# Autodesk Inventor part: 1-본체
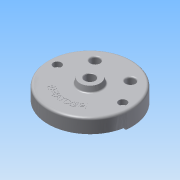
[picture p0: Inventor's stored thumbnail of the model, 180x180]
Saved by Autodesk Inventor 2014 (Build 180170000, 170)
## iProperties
Created: 2015-06
Part Number: 1-본체
Material: 알루미늄 6061
Document SubType Name: Modeling
Designer: Administrator
Density: 2.71 g/cm^3
Appearance: 알루미늄 - 평지
Mass: 1431.69 g
Surface Area: 1069.45 cm^2
Volume: 528.298 cm^3
Author: Administrator
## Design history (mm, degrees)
sketch "스케치1"
  geometry: C1 r 95 at (0, 0); 1 further point
  constraints: 1 centre point, 1 coincident
  dimensions: "d0" = 190 diameter of C1
extrude "돌출1" new body sketch "스케치1" distance "d1" = 32; taper "d2" = 0 deg
feature "쉘1" dims "d3" = 19, "d4" = 5
sketch "스케치2"
  geometry: C1 r 95 at (0, 0) reference; C2 r 26 at (0, 0)
  constraints: 1 centre point, 1 coincident
  dimensions: "d5" = 52 diameter of C2
extrude "돌출2" join sketch "스케치2" distance "d6" = 12; taper "d7" = -15 deg
sketch "스케치3"
  geometry: C1 r 90 at (0, 0) reference; C2 r 35 at (0, 0)
  constraints: 1 centre point, 1 coincident
  dimensions: "d8" = 70 diameter of C2
extrude "돌출3" join sketch "스케치3" distance "d9" = 10; taper "d10" = 0 deg
hole "구멍1" diameter "d13" = 23; stored, may be unused: countersink angle "d17" = 90 deg, drill point angle "d19" = 0 deg; dims "d11" = 10, "d12" = 10, "d14" = 6, "d15" = 50, "d16" = 15, "d18" = 8
sketch "스케치4"
  geometry: L1 (-45.033, 16)-(-75.657, 16); L2 (45.033, 16)-(75.657, 16); C1 r 95 at (0, 0) reference; A1 r 90 centre (0, 0) between (-88.566, 16) and (88.566, 16) reference; A2 r 42 centre (0, 0) between (36.373, 21) and (-36.373, 21); A3 r 90 centre (0, 0) between (85.114, 29.25) and (-85.114, 29.25); A4 r 10 centre (-75.657, 26) between (-85.114, 29.25) and (-75.657, 16); A5 r 10 centre (75.657, 26) between (75.657, 16) and (85.114, 29.25); A6 r 10 centre (-45.033, 26) between (-45.033, 16) and (-36.373, 21); A7 r 10 centre (45.033, 26) between (36.373, 21) and (45.033, 16); 2 further points
  constraints: 18 point on circle, 8 tangent, 6 centre point, 4 end point, 4 point on line, 3 equal radius, 2 coincident, 2 collinear, 1 horizontal
  dimensions: "d20" = 84 diameter of A2; "d21" = 16 distance from line of A1.centre L1; "d22" = 10 radius of A4; "d23" = 10 radius of A6
extrude "돌출4" cut sketch "스케치4" distance "d24" = 20; taper "d25" = 0 deg
sketch "스케치5"
  geometry: L1 (-45.033, 16)-(-75.657, 16) reference; L2 (-59, -19)-(59, -19); L3 (-59, -19)-(-59, -14); L4 (-41, -19)-(-41, -14); L5 (0, -19)-(0, 0); L6 (59, -19)-(59, -14); L7 (41, -19)-(41, -14); C1 r 35 at (0, 0) reference; A1 r 90 centre (0, 0) between (-85.114, 29.25) and (85.114, 29.25) reference; A2 r 41 centre (0, -19) between (-41, -19) and (41, -19); A3 r 59 centre (0, -19) between (-59, -19) and (59, -19); A4 r 9 centre (-50, -14) between (-41, -14) and (-59, -14); A5 r 9 centre (50, -14) between (59, -14) and (41, -14)
  constraints: 12 end point, 8 point on circle, 4 centre point, 4 parallel, 4 tangent, 3 symmetric about line, 2 point on line, 1 coincident, 1 perpendicular, 1 vertical alignment, 1 other
  dimensions: "d27" = 19 distance of A2.centre A1.centre; "d29" = 5 distance of L2.start L3.end; "d30" = 41 radius of A2; "d31" = 59 radius of A3
extrude "돌출5" cut sketch "스케치5" distance "d32" = 7; taper "d33" = 0 deg
sketch "스케치6"
  geometry: C1 r 90 at (0, 0) reference; C2 r 9 at (-74, 0); C3 r 9 at (74, 0)
  constraints: 2 centre point, 2 horizontal alignment, 1 equal radius
  dimensions: "d34" = 18 diameter of C2; "d35" = 148 distance of C3.centre C2.centre; "d36" = 74 distance of C3.centre C1.centre
extrude "돌출6" join sketch "스케치6" stored distance "d37" = 7; taper "d38" = 0 deg
sketch "스케치7"
  geometry: C1 r 9 at (-74, 0) reference; C2 r 9 at (74, 0) reference; 2 further points
  constraints: 2 coincident
hole "구멍2" sketch "스케치7" at (-74, 0), (74, 0) diameter "d39" = 11; stored, may be unused: countersink angle "d43" = 90 deg, drill point angle "d45" = 0 deg; dims "d40" = 6, "d41" = 18, "d42" = 11, "d44" = 8
sketch "스케치8"
  geometry: C1 r 90 at (0, 0); C2 r 15 at (-40, 52); C3 r 15 at (40, 52); C4 r 9 at (-74, 0)
  constraints: 4 centre point, 1 equal radius, 1 horizontal alignment
  dimensions: "d46" = 52 vertical distance of C4.centre C2.centre; "d47" = 30 diameter of C2; "d48" = 80 distance of C3.centre C2.centre; "d49" = 40 horizontal distance of C1.centre C2.centre
extrude "돌출7" join sketch "스케치8" stored distance "d50" = 7; taper "d51" = 0 deg
sketch "스케치15"
  geometry: C1 r 15 at (0, 0) reference; C2 r 15 at (80, 0) reference; C3 r 15 at (0, 0); C4 r 15 at (80, 0); 1 further point
  constraints: 2 centre point, 2 coincident, 2 concentric
  node "투영된 루프3"
sketch "스케치9"
  geometry: C1 r 15 at (0, 0) reference; C2 r 15 at (80, 0) reference; 3 further points
  constraints: 2 coincident
hole "구멍3" sketch "스케치9" at (0, 0), (80, 0) diameter "d52" = 20; stored, may be unused: countersink angle "d56" = 90 deg, drill point angle "d58" = 0 deg; dims "d53" = 6, "d54" = 18, "d55" = 11, "d57" = 8
sketch "스케치11"
  geometry: L1 (-95, 0)-(95, 0); L2 (-94.075, -13.221)-(-89.124, -12.526); L3 (89.124, -12.526)-(94.075, -13.221); A1 r 90 centre (0, 0) between (-89.124, -12.526) and (89.124, -12.526) reference; A2 r 95 centre (0, 0) between (-95, 0) and (95, 0) reference
  constraints: 6 end point, 6 point on circle, 1 horizontal
  dimensions: "d63" = 8 deg angle of L2 L1; "d64" = 8 deg angle of L3 L1; "d65" = 0 distance from line of A2.centre L3; "d66" = 0 distance from line of A2.centre L1; "d67" = 0 distance from line of A2.centre L2
extrude "돌출9" join sketch "스케치11" distance "d68" = 5; taper "d69" = 0 deg
sketch "스케치12"
  geometry: C1 r 9 at (-74, 0) reference; C2 r 5.5 at (74, 0) reference; C3 r 9 at (74, 0) reference; C4 r 9 at (-74, 0); C5 r 9 at (74, 0); C6 r 5.5 at (74, 0); C7 r 5.5 at (-74, 0) reference; C8 r 5.5 at (-74, 0)
  constraints: 4 centre point, 4 coincident, 4 concentric
extrude "돌출10" join sketch "스케치12" distance "d70" = 5; taper "d71" = 0 deg
fillet "모깎기1" dims "d72" = 3, "d73" = 5, "d74" = 1
chamfer "모따기1" distance "d75" = 1; stored, may be unused: second distance "d76" = 2, angle "d77" = 45 deg
sketch "스케치13"
  geometry: C1 r 90 at (0, 0) reference; C2 r 68 at (0, 0)
  constraints: 1 centre point, 1 coincident, 1 other
  dimensions: "d78" = 136 diameter of C2
feature "엠보싱1" sketch "스케치13" dims "d79" = 0.5, "d80" = 0
extrude "돌출11" join sketch "스케치15" distance "d82" = 5; taper "d83" = 0 deg
sketch "스케치16"
  geometry: C1 r 15 at (0, 0) reference; C2 r 15 at (80, 0) reference; 3 further points
  constraints: 2 coincident
hole "구멍4" sketch "스케치16" at (0, 0), (80, 0) diameter "d84" = 20; stored, may be unused: countersink angle "d88" = 90 deg, drill point angle "d90" = 118 deg; dims "d85" = 6, "d86" = 4, "d87" = 2, "d89" = 8
sketch "스케치17"
  geometry: L1 (-6, 13.748)-(-6, -13.748); L2 (6, 13.748)-(6, -13.748); A1 r 15 centre (0, 0) between (-6, 13.748) and (-6, -13.748) reference; 1 further point
  constraints: 4 end point, 4 point on circle, 1 parallel, 1 vertical
  dimensions: "d91" = 12 distance between parallel lines of L2 L1
extrude "돌출12" cut sketch "스케치17" distance "d92" = 3; taper "d93" = 0 deg
sketch "스케치18"
  geometry: L1 (-13.428, 6.684)-(14.032, 5.301); L2 (-14.032, -5.301)-(13.428, -6.684); A1 r 15 centre (0, 0) between (-13.428, 6.684) and (14.032, 5.301) reference; 1 further point
  constraints: 4 end point, 4 point on circle, 2 parallel
  dimensions: "d94" = 12 distance between parallel lines of L2 L1; "d96" = 59.94662 distance from line of point (-40, -52) L1
extrude "돌출13" cut sketch "스케치18" distance "d97" = 3; taper "d98" = 0 deg
sketch "스케치19"
  geometry: L1 (-45.033, 16)-(-75.657, 16) reference; L2 (75.657, 16)-(45.033, 16) reference; L3 (-45.033, 16)-(-75.657, 16) reference; L4 (75.657, 16)-(45.033, 16) reference; C1 r 18 at (-40, 52) reference; C2 r 18 at (40, 52) reference; A1 r 10 centre (-75.657, 26) between (-85.114, 29.25) and (-75.657, 16) reference; A2 r 10 centre (-45.033, 26) between (-45.033, 16) and (-36.373, 21) reference; A3 r 42 centre (0, 0) between (36.373, 21) and (-36.373, 21) reference; A4 r 10 centre (45.033, 26) between (36.373, 21) and (45.033, 16) reference; A5 r 10 centre (75.657, 26) between (75.657, 16) and (85.114, 29.25) reference; A6 r 90 centre (0, 0) between (85.114, 29.25) and (-85.114, 29.25) reference; A7 r 10 centre (-45.033, 26) between (-45.033, 16) and (-36.373, 21) reference; A8 r 42 centre (0, 0) between (36.373, 21) and (-36.373, 21) reference; A9 r 10 centre (45.033, 26) between (36.373, 21) and (45.033, 16) reference; A10 r 90 centre (0, 0) between (85.114, 29.25) and (-85.114, 29.25) reference; A11 r 10 centre (-75.657, 26) between (-85.114, 29.25) and (-75.657, 16) reference; A12 r 10 centre (75.657, 26) between (75.657, 16) and (85.114, 29.25) reference
extrude "돌출14" cut sketch "스케치19" distance "d99" = 5; taper "d100" = 0 deg
sketch "스케치20"
  geometry: C1 r 18 at (0, 0) reference; C2 r 15 at (0, 0) reference; C3 r 15 at (-80, 0) reference; C4 r 18 at (-80, 0) reference; 1 further point
extrude "돌출15" cut sketch "스케치20" distance "d101" = 5; taper "d102" = 0 deg
fillet "모깎기2" dims "d103" = 3
node "솔리드1"
node "투영된 루프1"
node "투영된 루프4"
node "투영된 루프5"
other parameters: "d26" = 82, "d28" = 118
